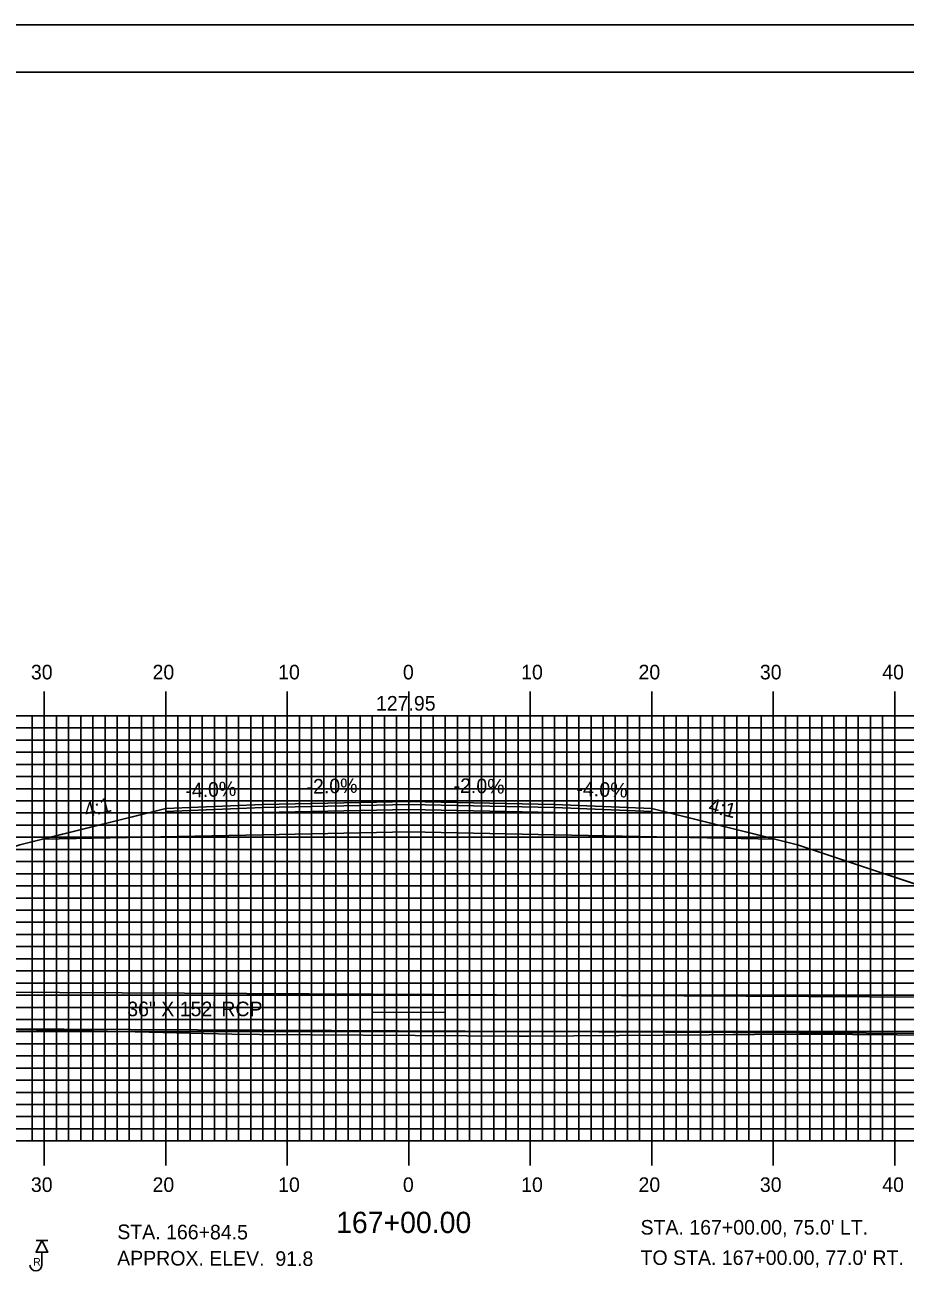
# Model space of a CAD drawing. Extents: x 1781467 to 1781810, y 442591 to 442811.
# Drawn here: x 1781600.8 to 1781673.3, y 442707.7 to 442810.5 of the extents above; entities that cross this region are included whole.
import ezdxf

# ---------------------------------------------------------------- set-up
doc = ezdxf.new("R2010")
doc.units = 0
for name, color, linetype in [('ANNOTATION', 7, 'Continuous'), ('BORDER', 7, 'Continuous'), ('BORING - REFUSAL', 7, 'Continuous'), ('D_Drainage_Culvert', 7, 'Continuous'), ('D_Drainage_Text', 7, 'Continuous'), ('D_Roadway_Centerline', 7, 'Continuous'), ('D_Roadway_Centerline_Text', 7, 'Continuous'), ('D_Roadway_Edge_Shoulder', 7, 'Continuous'), ('D_Roadway_Edge_TW', 7, 'Continuous'), ('D_Roadway_Pavement', 7, 'Continuous'), ('D_Roadway_SlopeLines', 7, 'Continuous'), ('D_Roadway_SubGrade', 7, 'Continuous'), ('D_Text_Standard', 7, 'Continuous'), ('H_V ANNOTATION', 7, 'Continuous'), ('MAJOR', 7, 'Continuous'), ('MINOR', 7, 'Continuous'), ('PLOT BOUNDARY', 7, 'Continuous'), ('S_Roadway_Centerline', 7, 'Continuous')]:
    doc.layers.add(name, color=color, linetype=linetype)

msp = doc.modelspace()

# ---------------------------------------------------------------- linework, layer by layer
at = {"layer": 'BORDER'}
msp.add_lwpolyline([(1781482.81, 442596.67), (1781802.81, 442596.67), (1781802.81, 442806.67), (1781482.81, 442806.67)], close=True, dxfattribs=at)
at = {"layer": 'BORING - REFUSAL'}
for p, q in [((1781602.69, 442710.47), (1781601.73, 442710.47)), ((1781602.21, 442709.51), (1781602.21, 442708.45))]:
    msp.add_line(p, q, dxfattribs=at)
msp.add_lwpolyline([(1781602.21, 442710.47), (1781602.69, 442709.51), (1781601.73, 442709.51)], close=True, dxfattribs=at)
msp.add_arc((1781601.72, 442708.45), 0.485, 180, 0, dxfattribs=at)
at = {"layer": 'D_Drainage_Culvert'}
for p, q in [((1781559.42, 442731.11), (1781707.42, 442730.34)), ((1781559.42, 442731.11), (1781707.42, 442730.34)), ((1781629.4, 442729.26), (1781635.4, 442729.24)), ((1781559.41, 442728.11), (1781707.4, 442727.34)), ((1781559.41, 442728.11), (1781707.4, 442727.34))]:
    msp.add_line(p, q, dxfattribs=at)
at = {"layer": 'D_Roadway_Centerline'}
msp.add_lwpolyline([(1781664.41, 442743.05), (1781699.13, 442731.48)], dxfattribs=at)
at = {"layer": 'D_Roadway_Edge_Shoulder'}
for points in [[(1781620.41, 442746.37), (1781612.41, 442746.05), (1781612.41, 442745.8), (1781620.41, 442746.12)], [(1781644.41, 442746.37), (1781652.41, 442746.05), (1781652.41, 442745.8), (1781644.41, 442746.12)]]:
    msp.add_lwpolyline(points, close=True, dxfattribs=at)
at = {"layer": 'D_Roadway_Edge_TW'}
msp.add_lwpolyline([(1781620.41, 442746.12), (1781620.41, 442746.37), (1781632.41, 442746.61), (1781644.41, 442746.37), (1781644.41, 442746.12), (1781632.41, 442746.36)], close=True, dxfattribs=at)
at = {"layer": 'D_Roadway_Pavement'}
msp.add_lwpolyline([(1781620.41, 442745.71), (1781620.41, 442746.12), (1781632.41, 442746.36), (1781644.41, 442746.12), (1781644.41, 442745.71), (1781632.41, 442745.95)], close=True, dxfattribs=at)
at = {"layer": 'D_Roadway_SlopeLines'}
for points in [[(1781612.41, 442746.05), (1781600.41, 442743.05), (1781574.65, 442734.47)], [(1781652.41, 442746.05), (1781664.41, 442743.05), (1781694.17, 442733.13)]]:
    msp.add_lwpolyline(points, dxfattribs=at)
at = {"layer": 'D_Roadway_SubGrade'}
msp.add_lwpolyline([(1781620.41, 442743.87), (1781602.23, 442743.51), (1781612.41, 442746.05), (1781612.41, 442745.8), (1781620.41, 442746.12), (1781632.41, 442746.36), (1781644.41, 442746.12), (1781652.41, 442745.8), (1781652.41, 442746.05), (1781662.58, 442743.51), (1781644.41, 442743.87), (1781632.41, 442744.11)], close=True, dxfattribs=at)
at = {"layer": 'MAJOR'}
for p, q in [((1781602.41, 442755.67), (1781602.41, 442753.67)), ((1781612.41, 442755.67), (1781612.41, 442753.67)), ((1781622.41, 442755.67), (1781622.41, 442753.67)), ((1781632.41, 442755.67), (1781632.41, 442753.67)), ((1781642.41, 442755.67), (1781642.41, 442753.67)), ((1781652.41, 442755.67), (1781652.41, 442753.67)), ((1781662.41, 442755.67), (1781662.41, 442753.67)), ((1781672.41, 442755.67), (1781672.41, 442753.67)), ((1781492.41, 442753.67), (1781772.41, 442753.67)), ((1781492.41, 442753.67), (1781772.41, 442753.67)), ((1781602.41, 442718.67), (1781602.41, 442753.67)), ((1781612.41, 442718.67), (1781612.41, 442753.67)), ((1781622.41, 442718.67), (1781622.41, 442753.67)), ((1781632.41, 442718.67), (1781632.41, 442753.67)), ((1781642.41, 442718.67), (1781642.41, 442753.67)), ((1781652.41, 442718.67), (1781652.41, 442753.67)), ((1781662.41, 442718.67), (1781662.41, 442753.67)), ((1781672.41, 442718.67), (1781672.41, 442753.67)), ((1781492.41, 442748.67), (1781772.41, 442748.67)), ((1781492.41, 442743.67), (1781772.41, 442743.67)), ((1781492.41, 442738.67), (1781772.41, 442738.67)), ((1781492.41, 442733.67), (1781772.41, 442733.67)), ((1781492.41, 442728.67), (1781772.41, 442728.67)), ((1781492.41, 442723.67), (1781772.41, 442723.67)), ((1781492.41, 442718.67), (1781772.41, 442718.67)), ((1781492.41, 442718.67), (1781772.41, 442718.67)), ((1781602.41, 442716.66), (1781602.41, 442718.67)), ((1781612.41, 442716.66), (1781612.41, 442718.67)), ((1781622.41, 442716.66), (1781622.41, 442718.67)), ((1781632.41, 442716.66), (1781632.41, 442718.67)), ((1781642.41, 442716.66), (1781642.41, 442718.67)), ((1781652.41, 442716.66), (1781652.41, 442718.67)), ((1781662.41, 442716.66), (1781662.41, 442718.67)), ((1781672.41, 442716.66), (1781672.41, 442718.67))]:
    msp.add_line(p, q, dxfattribs=at)
at = {"layer": 'MINOR'}
for p, q in [((1781601.41, 442718.67), (1781601.41, 442753.67)), ((1781603.41, 442718.67), (1781603.41, 442753.67)), ((1781604.41, 442718.67), (1781604.41, 442753.67)), ((1781605.41, 442718.67), (1781605.41, 442753.67)), ((1781606.41, 442718.67), (1781606.41, 442753.67)), ((1781607.41, 442718.67), (1781607.41, 442753.67)), ((1781608.41, 442718.67), (1781608.41, 442753.67)), ((1781609.41, 442718.67), (1781609.41, 442753.67)), ((1781610.41, 442718.67), (1781610.41, 442753.67)), ((1781611.41, 442718.67), (1781611.41, 442753.67)), ((1781613.41, 442718.67), (1781613.41, 442753.67)), ((1781614.41, 442718.67), (1781614.41, 442753.67)), ((1781615.41, 442718.67), (1781615.41, 442753.67)), ((1781616.41, 442718.67), (1781616.41, 442753.67)), ((1781617.41, 442718.67), (1781617.41, 442753.67)), ((1781618.41, 442718.67), (1781618.41, 442753.67)), ((1781619.41, 442718.67), (1781619.41, 442753.67)), ((1781620.41, 442718.67), (1781620.41, 442753.67)), ((1781621.41, 442718.67), (1781621.41, 442753.67)), ((1781623.41, 442718.67), (1781623.41, 442753.67)), ((1781624.41, 442718.67), (1781624.41, 442753.67)), ((1781625.41, 442718.67), (1781625.41, 442753.67)), ((1781626.41, 442718.67), (1781626.41, 442753.67)), ((1781627.41, 442718.67), (1781627.41, 442753.67)), ((1781628.41, 442718.67), (1781628.41, 442753.67)), ((1781629.41, 442718.67), (1781629.41, 442753.67)), ((1781630.41, 442718.67), (1781630.41, 442753.67)), ((1781631.41, 442718.67), (1781631.41, 442753.67)), ((1781633.41, 442718.67), (1781633.41, 442753.67)), ((1781634.41, 442718.67), (1781634.41, 442753.67)), ((1781635.41, 442718.67), (1781635.41, 442753.67)), ((1781636.41, 442718.67), (1781636.41, 442753.67)), ((1781637.41, 442718.67), (1781637.41, 442753.67)), ((1781638.41, 442718.67), (1781638.41, 442753.67)), ((1781639.41, 442718.67), (1781639.41, 442753.67)), ((1781640.41, 442718.67), (1781640.41, 442753.67)), ((1781641.41, 442718.67), (1781641.41, 442753.67)), ((1781643.41, 442718.67), (1781643.41, 442753.67)), ((1781644.41, 442718.67), (1781644.41, 442753.67)), ((1781645.41, 442718.67), (1781645.41, 442753.67)), ((1781646.41, 442718.67), (1781646.41, 442753.67)), ((1781647.41, 442718.67), (1781647.41, 442753.67)), ((1781648.41, 442718.67), (1781648.41, 442753.67)), ((1781649.41, 442718.67), (1781649.41, 442753.67)), ((1781650.41, 442718.67), (1781650.41, 442753.67)), ((1781651.41, 442718.67), (1781651.41, 442753.67)), ((1781653.41, 442718.67), (1781653.41, 442753.67)), ((1781654.41, 442718.67), (1781654.41, 442753.67)), ((1781655.41, 442718.67), (1781655.41, 442753.67)), ((1781656.41, 442718.67), (1781656.41, 442753.67)), ((1781657.41, 442718.67), (1781657.41, 442753.67)), ((1781658.41, 442718.67), (1781658.41, 442753.67)), ((1781659.41, 442718.67), (1781659.41, 442753.67)), ((1781660.41, 442718.67), (1781660.41, 442753.67)), ((1781661.41, 442718.67), (1781661.41, 442753.67)), ((1781663.41, 442718.67), (1781663.41, 442753.67)), ((1781664.41, 442718.67), (1781664.41, 442753.67)), ((1781665.41, 442718.67), (1781665.41, 442753.67)), ((1781666.41, 442718.67), (1781666.41, 442753.67)), ((1781667.41, 442718.67), (1781667.41, 442753.67)), ((1781668.41, 442718.67), (1781668.41, 442753.67)), ((1781669.41, 442718.67), (1781669.41, 442753.67)), ((1781670.41, 442718.67), (1781670.41, 442753.67)), ((1781671.41, 442718.67), (1781671.41, 442753.67)), ((1781492.41, 442752.67), (1781772.41, 442752.67)), ((1781492.41, 442751.67), (1781772.41, 442751.67)), ((1781492.41, 442750.67), (1781772.41, 442750.67)), ((1781492.41, 442749.67), (1781772.41, 442749.67)), ((1781492.41, 442747.67), (1781772.41, 442747.67)), ((1781492.41, 442746.67), (1781772.41, 442746.67)), ((1781492.41, 442745.67), (1781772.41, 442745.67)), ((1781492.41, 442744.67), (1781772.41, 442744.67)), ((1781492.41, 442742.67), (1781772.41, 442742.67)), ((1781492.41, 442741.67), (1781772.41, 442741.67)), ((1781492.41, 442740.67), (1781772.41, 442740.67)), ((1781492.41, 442739.67), (1781772.41, 442739.67)), ((1781492.41, 442737.67), (1781772.41, 442737.67)), ((1781492.41, 442736.67), (1781772.41, 442736.67)), ((1781492.41, 442735.67), (1781772.41, 442735.67)), ((1781492.41, 442734.67), (1781772.41, 442734.67)), ((1781492.41, 442732.67), (1781772.41, 442732.67)), ((1781492.41, 442731.67), (1781772.41, 442731.67)), ((1781492.41, 442730.67), (1781772.41, 442730.67)), ((1781492.41, 442729.67), (1781772.41, 442729.67)), ((1781492.41, 442727.67), (1781772.41, 442727.67)), ((1781492.41, 442726.67), (1781772.41, 442726.67)), ((1781492.41, 442725.67), (1781772.41, 442725.67)), ((1781492.41, 442724.67), (1781772.41, 442724.67)), ((1781492.41, 442722.67), (1781772.41, 442722.67)), ((1781492.41, 442721.67), (1781772.41, 442721.67)), ((1781492.41, 442720.67), (1781772.41, 442720.67)), ((1781492.41, 442719.67), (1781772.41, 442719.67))]:
    msp.add_line(p, q, dxfattribs=at)
at = {"layer": 'PLOT BOUNDARY'}
msp.add_lwpolyline([(1781466.62, 442590.55), (1781806.62, 442590.55), (1781806.62, 442810.55), (1781466.62, 442810.55)], close=True, dxfattribs=at)
at = {"layer": 'S_Roadway_Centerline'}
msp.add_lwpolyline([(1781593.87, 442727.96), (1781606.48, 442727.73), (1781617.86, 442727.47), (1781620.12, 442727.44), (1781641.46, 442727.3), (1781641.85, 442727.29), (1781642.28, 442727.3), (1781664.58, 442727.45), (1781665.29, 442727.46), (1781676.24, 442727.38), (1781688.68, 442727.78), (1781690.56, 442727.77), (1781710.17, 442727.27), (1781711.23, 442727.28), (1781712.29, 442727.33), (1781733.34, 442727.58), (1781736.01, 442727.52), (1781754.54, 442727.3), (1781758.15, 442727.36), (1781769.13, 442727.64), (1781772.41, 442727.64)], dxfattribs=at)

# ---------------------------------------------------------------- texts
at = {"layer": 'ANNOTATION'}
for s, rotation, p in [('-4.0%', 2.2906, (1781614.04, 442746.92)), ('-2.0%', 1.1458, (1781624.01, 442747.25)), ('-2.0%', 358.8542, (1781636.09, 442747.34)), ('-4.0%', 357.7094, (1781646.2, 442747.1)), ('4:1', 14.0362, (1781605.86, 442745.28)), ('4:1', 345.9638, (1781657, 442745.77))]:
    msp.add_text(s, height=1.2, rotation=rotation, dxfattribs=at).set_placement(p)
at = {"layer": 'BORING - REFUSAL'}
for s, p in [('STA. 166+84.5', (1781608.42, 442710.59)), ('APPROX. ELEV.  91.8', (1781608.41, 442708.43))]:
    msp.add_text(s, height=1.2, rotation=359.8142, dxfattribs=at).set_placement(p)
msp.add_text('R', height=0.64, dxfattribs=at).set_placement((1781601.5, 442708.39))
at = {"layer": 'D_Drainage_Text'}
msp.add_text('36" X 152\' RCP ', height=1.2, dxfattribs=at).set_placement((1781609.24, 442728.94))
at = {"layer": 'D_Roadway_Centerline'}
for s, p in [('C', (1781632.4, 442746.61)), ('L', (1781632.41, 442746.61))]:
    msp.add_text(s, height=0.0146, dxfattribs=at).set_placement(p)
at = {"layer": 'D_Roadway_Centerline_Text'}
msp.add_text('127.95', height=1.2, dxfattribs=at).set_placement((1781629.71, 442754.1))
at = {"layer": 'D_Text_Standard'}
for s, p in [("STA. 167+00.00, 75.0' LT.", (1781651.49, 442710.96)), ("TO STA. 167+00.00, 77.0' RT.", (1781651.49, 442708.46))]:
    msp.add_text(s, height=1.2, dxfattribs=at).set_placement(p)
at = {"layer": 'H_V ANNOTATION'}
for s, height, p in [('30', 1.2, (1781601.31, 442756.67)), ('20', 1.2, (1781611.32, 442756.67)), ('10', 1.2, (1781621.66, 442756.67)), ('0', 1.2, (1781631.93, 442756.67)), ('10', 1.2, (1781641.66, 442756.67)), ('20', 1.2, (1781651.32, 442756.67)), ('30', 1.2, (1781661.31, 442756.67)), ('40', 1.2, (1781671.38, 442756.67)), ('30', 1.2, (1781601.31, 442714.47)), ('20', 1.2, (1781611.32, 442714.47)), ('10', 1.2, (1781621.66, 442714.47)), ('0', 1.2, (1781631.93, 442714.47)), ('10', 1.2, (1781641.66, 442714.47)), ('20', 1.2, (1781651.32, 442714.47)), ('30', 1.2, (1781661.31, 442714.47)), ('40', 1.2, (1781671.38, 442714.47)), ('167+00.00', 1.75, (1781626.43, 442711.09))]:
    msp.add_text(s, height=height, dxfattribs=at).set_placement(p)

doc.saveas('drawing.dxf')
